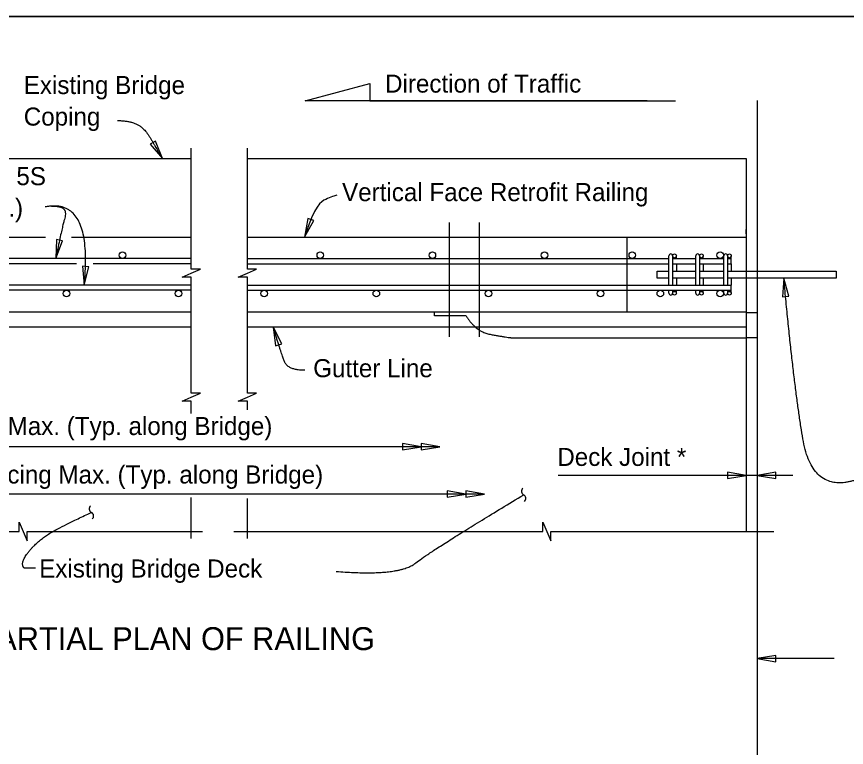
# Model space of a CAD drawing. Extents: x 0 to 41.1, y 0 to 25.9.
# Drawn here: x 7.16 to 16.42, y 17.79 to 25.95 of the extents above; entities that cross this region are included whole.
import ezdxf

# ---------------------------------------------------------------- set-up
doc = ezdxf.new("R2010")
doc.units = 0
for name, color, linetype in [('Dimension', 7, 'Continuous'), ('Miscellaneous', 7, 'Continuous'), ('Miscellaneous1', 7, 'Continuous'), ('Rebar', 7, 'Continuous'), ('TextStructures', 7, 'Continuous'), ('TrafBarrierConc', 7, 'Continuous')]:
    doc.layers.add(name, color=color, linetype=linetype)

msp = doc.modelspace()

# ---------------------------------------------------------------- linework, layer by layer
at = {"layer": 'Dimension'}
for p, q in [((10.3808, 25.0081), (11.1024, 25.1997)), ((11.1024, 25.1997), (11.1041, 25.0081)), ((14.1935, 25.0081), (10.3808, 25.0081)), ((11.1041, 25.0081), (14.3174, 25.0081)), ((14.3174, 25.0081), (14.5108, 25.0081)), ((11.9889, 23.6494), (11.9889, 22.373)), ((12.3223, 23.6494), (12.3223, 22.373)), ((11.8824, 21.1482), (4.0811, 21.1482)), ((15.82, 20.8284), (13.2019, 20.8284)), ((12.3805, 20.6203), (4.0811, 20.6203)), ((16.2803, 18.7846), (15.4221, 18.7846))]:
    msp.add_line(p, q, dxfattribs=at)
for points in [[(0, 0), (41.0507, 0), (41.0507, 25.9462), (0, 25.9462)], [(8.791, 24.3615), (8.7137, 24.5581), (8.6533, 24.5217)], [(10.373, 23.4867), (10.4769, 23.6706), (10.4105, 23.6946)], [(7.601, 23.2471), (7.6772, 23.4441), (7.608, 23.4582)], [(7.9177, 22.9502), (7.9679, 23.1554), (7.8976, 23.1605)], [(15.7188, 23.0296), (15.7027, 22.819), (15.773, 22.8255)], [(10.0243, 22.4842), (10.0523, 22.2748), (10.1197, 22.2958)], [(11.6741, 21.1482), (11.4659, 21.1834), (11.4659, 21.1129)], [(11.8824, 21.1482), (11.6741, 21.1834), (11.6741, 21.1129)], [(15.2997, 20.8284), (15.0915, 20.8637), (15.0915, 20.7931)], [(15.4222, 20.8284), (15.6305, 20.7931), (15.6305, 20.8637)], [(12.1723, 20.6203), (11.964, 20.6556), (11.964, 20.585)], [(12.3805, 20.6203), (12.1723, 20.6556), (12.1723, 20.585)], [(15.4221, 18.7846), (15.6304, 18.7493), (15.6304, 18.8199)]]:
    msp.add_lwpolyline(points, close=True, dxfattribs=at)
for points in [[(9.1115, 22.0358), (9.1115, 23.0389), (9.0082, 23.0389), (9.1115, 23.0839), (9.2149, 23.1289), (9.1115, 23.1289), (9.1115, 24.4781)], [(9.7369, 22.0358), (9.7369, 23.0389), (9.6336, 23.0389), (9.7369, 23.0839), (9.8402, 23.1289), (9.7369, 23.1289), (9.7369, 24.4781)], [(9.1115, 21.5182), (9.1115, 21.6559), (9.0082, 21.6559), (9.1115, 21.7009), (9.2149, 21.7459), (9.1115, 21.7459), (9.1115, 22.0358)], [(9.7369, 21.5576), (9.7369, 21.6559), (9.6336, 21.6559), (9.7369, 21.7009), (9.8402, 21.7459), (9.7369, 21.7459), (9.7369, 22.0358)], [(9.1115, 20.1231), (9.1115, 20.5799)], [(9.7369, 20.1231), (9.7369, 20.57)], [(5.7072, 20.203), (7.1934, 20.203), (7.1934, 20.3063), (7.2384, 20.203), (7.2834, 20.0997), (7.2834, 20.203), (9.2365, 20.203)], [(9.5877, 20.2031), (13.0313, 20.2031), (13.0313, 20.3064), (13.0763, 20.2031), (13.1213, 20.0997), (13.1213, 20.2031), (15.6079, 20.2031)]]:
    msp.add_lwpolyline(points, dxfattribs=at)
for centre, start, end in [((12.8386, 20.6513), 131.17199, 242.89921), ((12.7979, 20.5717), 311.17199, 62.89921), ((8.0184, 20.4549), 131.17199, 242.89921), ((7.9777, 20.3753), 311.17199, 62.89921)]:
    msp.add_arc(centre, 0.0447, start, end, dxfattribs=at)
for points, degree in [([(8.2882, 24.7868), (8.437, 24.7835), (8.5942, 24.6958), (8.7232, 24.4741), (8.791, 24.3615)], 2), ([(10.7356, 23.9525), (10.7089, 23.9473), (10.6252, 23.9192), (10.4887, 23.844), (10.3729, 23.4867)], 3), ([(7.9176, 22.9503), (8.0173, 23.9319), (7.4829, 23.8221)], 2), ([(7.5521, 23.832), (7.6515, 23.8337), (7.7235, 23.772), (7.6663, 23.5798), (7.6009, 23.2471)], 2), ([(16.5142, 20.7749), (16.0355, 20.624), (15.8277, 21.8442), (15.7188, 23.0296)], 2), ([(10.3795, 22.0011), (10.1836, 21.997), (10.1047, 22.2249), (10.0242, 22.4842)], 2), ([(10.7271, 19.7572), (11.4252, 19.7009), (11.7932, 19.9941), (12.8182, 20.6119)], 2), ([(7.3752, 19.7922), (7.2898, 19.7922), (7.2307, 19.7922), (7.2307, 19.8973), (7.4048, 20.1011), (7.6249, 20.2391), (7.9979, 20.4156)], 2)]:
    msp.add_open_spline(points, degree=degree, dxfattribs=at)
at = {"layer": 'Miscellaneous'}
for p, q in [((15.4221, 25.0108), (15.4221, 10.2577)), ((11.8223, 22.6076), (11.8223, 22.6534)), ((12.1766, 22.6076), (11.8223, 22.6076)), ((12.6995, 22.3617), (15.2996, 22.3627))]:
    msp.add_line(p, q, dxfattribs=at)
for centre, radius, start, end in [((15.2609, 209.6464), 187, 270.011099, 270.050528), ((15.2609, 209.657), 187.291, 270.011082, 270.049639)]:
    msp.add_arc(centre, radius, start, end, dxfattribs=at)
msp.add_open_spline([(12.1766, 22.6077), (12.2831, 22.431), (12.6245, 22.3682), (12.6995, 22.3617)], degree=2, dxfattribs=at)
at = {"layer": 'Miscellaneous1'}
msp.add_lwpolyline([(0, 25.9462), (41.0507, 25.9462), (41.0507, 0), (0, 0)], close=True, dxfattribs=at)
at = {"layer": 'Rebar'}
for p, q in [((9.1115, 23.2471), (4.4329, 23.2471)), ((9.7369, 23.2471), (14.4372, 23.2471)), ((14.4372, 22.9503), (14.4372, 23.2771)), ((14.4789, 23.2771), (14.4789, 22.9503)), ((14.4789, 23.2471), (14.7371, 23.2471)), ((14.5206, 23.2471), (14.5206, 23.2771)), ((14.7371, 22.9503), (14.7371, 23.2771)), ((14.7788, 23.2771), (14.7788, 22.9503)), ((14.7788, 23.2471), (15.0496, 23.2471)), ((14.8204, 23.2471), (14.8204, 23.2771)), ((15.0496, 22.9503), (15.0496, 23.2771)), ((15.0913, 23.2771), (15.0913, 23.2175)), ((15.0913, 23.2471), (15.133, 23.2471)), ((15.1329, 23.2471), (15.1329, 23.2771)), ((15.133, 23.1898), (15.133, 23.2471)), ((7.8325, 23.1898), (4.4329, 23.1898)), ((9.1115, 23.1898), (8.0166, 23.1898)), ((9.7369, 23.1898), (14.4372, 23.1898)), ((14.4789, 23.1898), (14.7371, 23.1898)), ((14.5206, 23.1898), (14.5206, 23.1079)), ((14.7788, 23.1898), (15.0496, 23.1898)), ((14.8204, 23.1898), (14.8204, 23.1079)), ((15.0913, 23.2175), (15.0913, 22.9503)), ((15.0913, 23.1898), (15.133, 23.1898)), ((15.1329, 23.1898), (15.1329, 23.1079)), ((16.3025, 23.1077), (16.3025, 23.0296)), ((9.1115, 22.9503), (5.3466, 22.9503)), ((9.7369, 22.9503), (15.133, 22.9503)), ((14.5206, 23.0296), (14.5206, 22.9503)), ((14.8204, 23.0296), (14.8204, 22.9503)), ((15.1329, 23.0296), (15.1329, 22.9503)), ((15.133, 22.893), (15.133, 22.9503)), ((9.1115, 22.893), (3.7609, 22.893)), ((9.7369, 22.893), (15.133, 22.893)), ((14.4372, 22.8604), (14.4372, 22.893)), ((14.4789, 22.893), (14.4789, 22.8604)), ((14.5206, 22.8604), (14.5206, 22.893)), ((14.7371, 22.8604), (14.7371, 22.893)), ((14.7788, 22.893), (14.7788, 22.8604)), ((14.8204, 22.8604), (14.8204, 22.893)), ((15.0496, 22.8604), (15.0496, 22.893)), ((15.0913, 22.893), (15.0913, 22.8604)), ((15.1329, 22.8604), (15.1329, 22.893))]:
    msp.add_line(p, q, dxfattribs=at)
for points in [[(14.4372, 23.0296), (14.3049, 23.0296), (14.3049, 23.1077), (14.4372, 23.1077)], [(14.4789, 23.1077), (14.7371, 23.1077)], [(14.7788, 23.1077), (15.0496, 23.1077)], [(15.0913, 23.1077), (16.3025, 23.1077)], [(14.7371, 23.0296), (14.4789, 23.0296)], [(15.0496, 23.0296), (14.7788, 23.0296)], [(16.3025, 23.0296), (15.0913, 23.0296)]]:
    msp.add_lwpolyline(points, dxfattribs=at)
for centre, radius in [((8.344, 23.2836), 0.0365), ((10.5499, 23.2836), 0.0365), ((11.7999, 23.2836), 0.0365), ((13.0499, 23.2836), 0.0365), ((14.0289, 23.2836), 0.0365), ((15.0079, 23.2836), 0.0365), ((14.4997, 23.2771), 0.0208), ((14.7996, 23.2771), 0.0208), ((15.1121, 23.2771), 0.0208), ((7.719, 22.8565), 0.0365), ((8.969, 22.8565), 0.0365), ((9.9249, 22.8565), 0.0365), ((11.1749, 22.8565), 0.0365), ((12.4249, 22.8565), 0.0365), ((13.6749, 22.8565), 0.0365), ((14.3416, 22.8565), 0.0365), ((14.4997, 22.8604), 0.0208), ((14.7996, 22.8604), 0.0208), ((15.0079, 22.8565), 0.0365), ((15.1121, 22.8604), 0.0208)]:
    msp.add_circle(centre, radius, dxfattribs=at)
for centre, start, end in [((14.4581, 23.2771), 0, 180), ((14.7579, 23.2771), 0, 180), ((15.0704, 23.2771), 0, 180), ((14.4581, 22.8604), 180, 0), ((14.7579, 22.8604), 180, 0), ((15.0704, 22.8604), 180, 0)]:
    msp.add_arc(centre, 0.0208, start, end, dxfattribs=at)
at = {"layer": 'TrafBarrierConc'}
for p, q in [((1.6386, 24.362), (9.1115, 24.362)), ((9.7369, 24.362), (15.2996, 24.362)), ((15.2996, 24.362), (15.2996, 23.4867)), ((15.2996, 23.5241), (15.2996, 23.5702)), ((15.2996, 23.5702), (15.2996, 20.203)), ((3.5943, 23.4867), (7.4875, 23.4867)), ((7.777, 23.4867), (9.1115, 23.4867)), ((9.7369, 23.4867), (15.2996, 23.4867)), ((13.9663, 23.4867), (13.9663, 22.6534)), ((15.2996, 23.4867), (15.2996, 22.6534)), ((3.5942, 22.6534), (9.1115, 22.6534)), ((9.7369, 22.6534), (15.2996, 22.6534)), ((1.6386, 22.4867), (9.1115, 22.4867)), ((9.7369, 22.4867), (15.2996, 22.4867))]:
    msp.add_line(p, q, dxfattribs=at)

# ---------------------------------------------------------------- texts
at = {"layer": 'Dimension'}
for s, p in [('Existing Bridge ', (7.2435, 25.082)), ('Coping', (7.2435, 24.73)), ('Bars 5S', (6.5324, 24.0654)), ('(Typ.)', (6.5324, 23.7134))]:
    msp.add_text(s, height=0.2016, dxfattribs=at).set_placement(p)
at = {"layer": 'TextStructures'}
msp.add_text('Direction of Traffic', height=0.2016, rotation=359.99977, dxfattribs=at).set_placement((11.2722, 25.098))
for s, height, p in [('Vertical Face Retrofit Railing', 0.2016, (10.793, 23.8874)), ('Gutter Line', 0.2016, (10.4708, 21.9233)), ('1\'-3" Spacing Max. (Typ. along Bridge)', 0.2016, (5.4031, 21.2781)), ('Deck Joint *', 0.2016, (13.1928, 20.9336)), ('1\'-3" Spacing Max. (Typ. along Bridge)', 0.2016, (5.9697, 20.737)), ('Existing Bridge Deck', 0.2016, (7.4158, 19.6886)), ('PARTIAL PLAN OF RAILING', 0.256, (6.7089, 18.8787))]:
    msp.add_text(s, height=height, dxfattribs=at).set_placement(p)

doc.saveas('drawing.dxf')
